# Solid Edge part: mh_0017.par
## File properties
Title: stopper
Author: edge
Template: normal.par
Last saved by: edge
Revision: 33
Application: Solid Edge
Density: 0.001200 g/mm^3
Accuracy: 0.99
非切断部品: False
文書内容のタイプ: 0
Material: ABS
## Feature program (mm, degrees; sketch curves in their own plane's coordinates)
sketch for "unnamed Protrusion 1" plane through (0, 0, 0) normal (0, 0, 1) x-axis (1, 0, 0)
  line (0, 0) -> (50, 0)
  line (50, 0) -> (50, -80)
  line (50, -80) -> (0, -80)
  line (0, -80) -> (0, 0)
extrude "unnamed Protrusion 1" add finite 15 along +normal
thinwall "Thinwall_1"  Thickness = 1 mm
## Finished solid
Body 1: solid body, 11 faces, 24 edges, 16 vertices.
  Faces by surface: plane 11
  Edges by curve: line 24
Bounding box of the edges (mm): 50.000 x 80.000 x 15.000, from (0, -80, 0) to (50, 0, 15).
Planar faces by outward normal: +x 2, +y 2, +z 1, -x 2, -y 2, -z 2
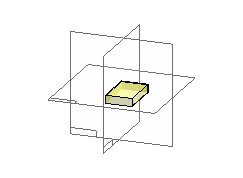
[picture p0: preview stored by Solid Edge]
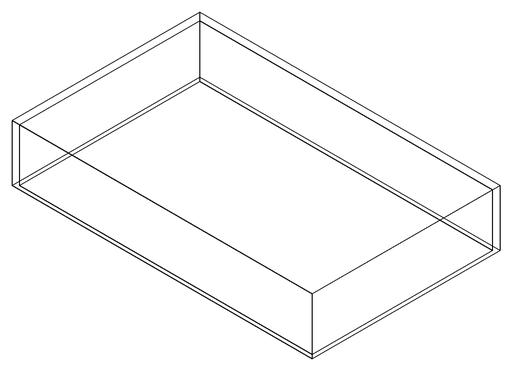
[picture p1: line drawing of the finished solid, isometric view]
